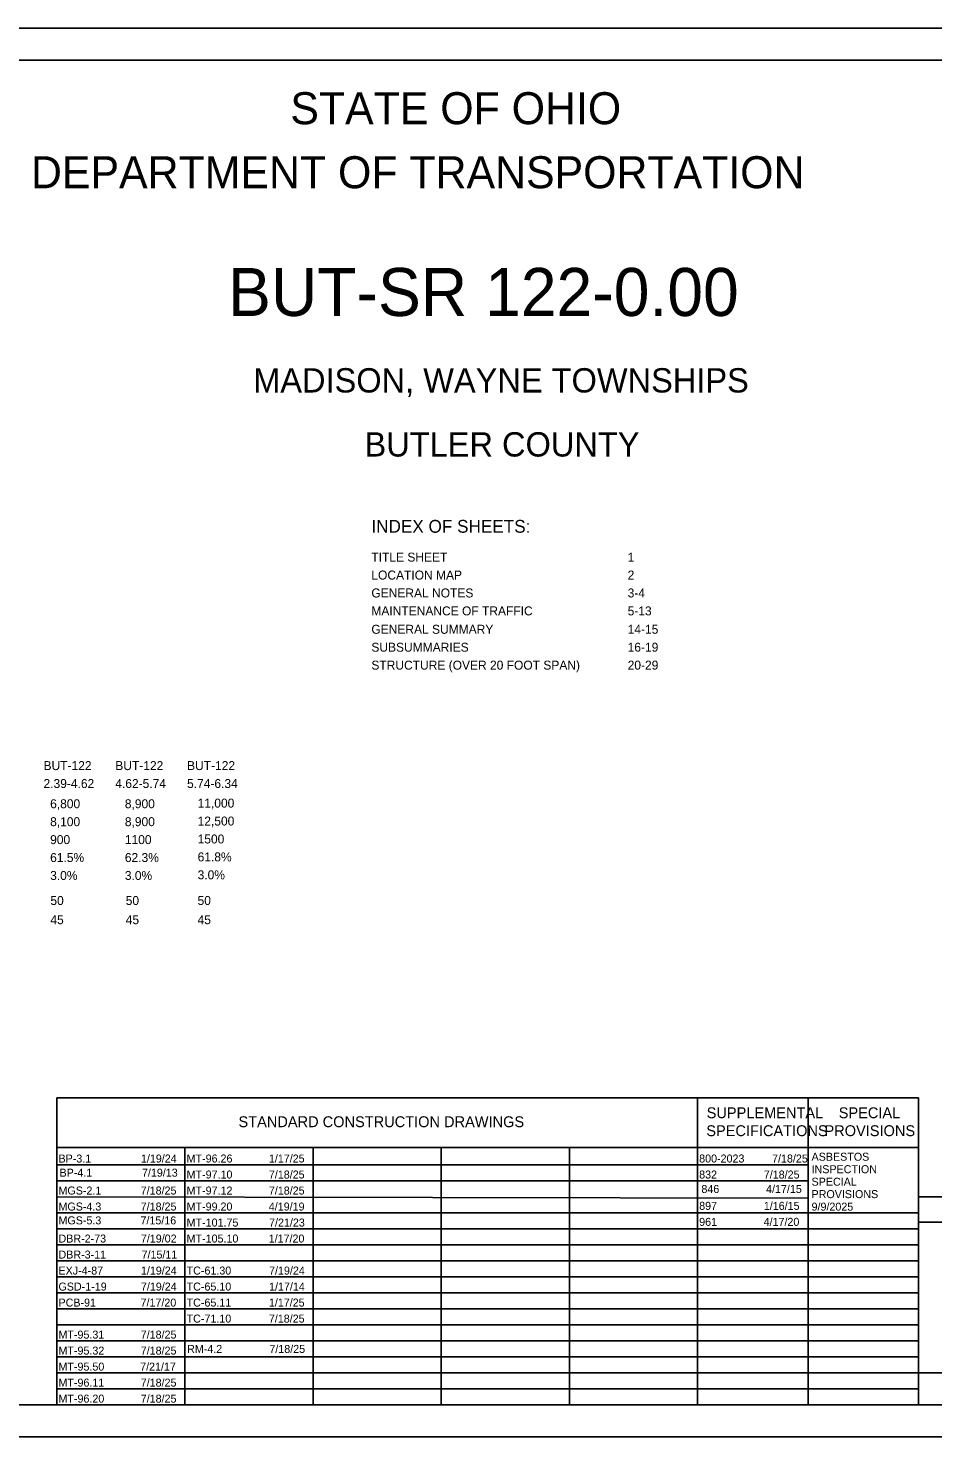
# Model space of a CAD drawing. Extents: x -11.1 to 43.5, y 0 to 22.
# Drawn here: x 9.7 to 23.82, y 0 to 22 of the extents above; entities that cross this region are included whole.
import ezdxf

# ---------------------------------------------------------------- set-up
doc = ezdxf.new("R2010")
doc.units = 0
for name, color, linetype in [('Default', 7, 'Continuous'), ('SH_Border', 7, 'Continuous'), ('SH_Cut_Line', 7, 'Continuous'), ('SH_Data', 7, 'Continuous'), ('SH_Text', 7, 'Continuous')]:
    doc.layers.add(name, color=color, linetype=linetype)

msp = doc.modelspace()

# ---------------------------------------------------------------- linework, layer by layer
at = {"layer": 'SH_Border'}
msp.add_lwpolyline([(1.5, 21.5), (33.5, 21.5), (33.5, 0.5), (1.5, 0.5)], close=True, dxfattribs=at)
at = {"layer": 'SH_Cut_Line'}
msp.add_lwpolyline([(0, 0), (34, 0), (34, 22), (0, 22)], close=True, dxfattribs=at)
at = {"layer": 'SH_Data'}
for p, q in [((10.15, 5.292), (23.6, 5.292)), ((10.15, 0.5), (10.15, 5.292)), ((20.15, 0.5), (20.15, 5.292)), ((21.875, 0.5), (21.875, 5.292)), ((23.6, 0.5), (23.6, 5.292)), ((10.15, 4.521), (23.6, 4.521)), ((12.15, 0.5), (12.15, 4.521)), ((14.15, 0.5), (14.15, 4.521)), ((16.15, 0.5), (16.15, 4.521)), ((18.15, 0.5), (18.15, 4.521)), ((10.15, 4.25), (21.875, 4.25)), ((10.15, 4), (21.875, 4)), ((10.15, 3.75), (21.875, 3.728)), ((23.6, 0.5), (23.6, 3.75)), ((23.6, 3.75), (26.4, 3.75)), ((10.15, 3.5), (23.6, 3.5)), ((23.6, 3.35), (26.4, 3.35)), ((10.15, 3.25), (23.6, 3.25)), ((10.15, 3), (23.6, 3)), ((10.15, 2.75), (23.6, 2.75)), ((10.15, 2.5), (23.6, 2.5)), ((10.15, 2.25), (23.6, 2.25)), ((10.15, 2), (23.6, 2)), ((10.15, 1.75), (23.6, 1.75)), ((10.15, 1.5), (23.6, 1.5)), ((10.15, 1.25), (23.6, 1.25)), ((10.15, 1), (23.6, 1)), ((10.15, 0.75), (23.6, 0.75)), ((23.6, 0.5), (26.4, 0.5))]:
    msp.add_line(p, q, dxfattribs=at)
msp.add_lwpolyline([(23.6, 0.5), (23.6, 1), (26.4, 1), (26.4, 0.5)], close=True, dxfattribs=at)

# ---------------------------------------------------------------- texts
at = {"layer": 'Default'}
for s, p in [('BP-3.1', (10.176, 4.284)), ('1/19/24', (11.463, 4.284)), ('MT-96.26', (12.176, 4.284)), ('1/17/25', (13.46, 4.284)), ('800-2023', (20.176, 4.284)), ('7/18/25', (21.314, 4.284)), ('BP-4.1', (10.192, 4.063)), ('7/19/13', (11.479, 4.063)), ('MT-97.10', (12.176, 4.034)), ('7/18/25', (13.46, 4.034)), ('832', (20.176, 4.034)), ('7/18/25', (21.185, 4.034)), ('MGS-2.1', (10.176, 3.784)), ('7/18/25', (11.46, 3.784)), ('MT-97.12', (12.176, 3.784)), ('7/18/25', (13.46, 3.784)), ('846', (20.211, 3.808)), ('4/17/15', (21.22, 3.808)), ('MGS-4.3', (10.176, 3.534)), ('7/18/25', (11.46, 3.534)), ('MT-99.20', (12.176, 3.534)), ('4/19/19', (13.459, 3.534)), ('897', (20.176, 3.545)), ('1/16/15', (21.185, 3.545)), ('MGS-5.3', (10.176, 3.318)), ('7/15/16', (11.456, 3.318)), ('MT-101.75', (12.176, 3.284)), ('7/21/23', (13.463, 3.284)), ('961', (20.176, 3.295)), ('4/17/20', (21.182, 3.295)), ('DBR-2-73', (10.176, 3.034)), ('7/19/02', (11.462, 3.034)), ('MT-105.10', (12.176, 3.034)), ('1/17/20', (13.457, 3.034)), ('DBR-3-11', (10.176, 2.784)), ('7/15/11', (11.473, 2.784)), ('EXJ-4-87', (10.176, 2.534)), ('1/19/24', (11.463, 2.534)), ('TC-61.30', (12.176, 2.534)), ('7/19/24', (13.463, 2.534)), ('GSD-1-19', (10.176, 2.284)), ('7/19/24', (11.463, 2.284)), ('TC-65.10', (12.176, 2.284)), ('1/17/14', (13.463, 2.284)), ('PCB-91', (10.176, 2.034)), ('7/17/20', (11.457, 2.034)), ('TC-65.11', (12.176, 2.034)), ('1/17/25', (13.46, 2.034)), ('TC-71.10', (12.176, 1.784)), ('7/18/25', (13.46, 1.784)), ('MT-95.31', (10.176, 1.534)), ('7/18/25', (11.46, 1.534)), ('MT-95.32', (10.176, 1.284)), ('7/18/25', (11.46, 1.284)), ('RM-4.2', (12.183, 1.31)), ('7/18/25', (13.468, 1.31)), ('MT-95.50', (10.176, 1.034)), ('7/21/17', (11.451, 1.034)), ('MT-96.11', (10.176, 0.784)), ('7/18/25', (11.46, 0.784)), ('MT-96.20', (10.176, 0.534)), ('7/18/25', (11.46, 0.534))]:
    msp.add_text(s, height=0.125, dxfattribs=at).set_placement(p)
at = {"layer": 'SH_Text'}
for s, height, p in [('STATE OF OHIO', 0.5, (13.795, 20.5)), ('DEPARTMENT OF TRANSPORTATION', 0.5, (9.747, 19.5)), ('BUT-SR 122-0.00', 0.75, (12.823, 17.505)), ('MADISON, WAYNE TOWNSHIPS', 0.38, (13.215, 16.31)), ('BUTLER COUNTY', 0.38, (14.953, 15.31)), ('INDEX OF SHEETS:', 0.2, (15.06, 14.12)), ('TITLE SHEET', 0.14, (15.06, 13.669)), ('1', 0.14, (19.06, 13.669)), ('LOCATION MAP', 0.14, (15.06, 13.389)), ('2', 0.14, (19.06, 13.389)), ('GENERAL NOTES', 0.14, (15.06, 13.109)), ('3-4', 0.14, (19.06, 13.109)), ('MAINTENANCE OF TRAFFIC', 0.14, (15.06, 12.829)), ('5-13', 0.14, (19.06, 12.829)), ('GENERAL SUMMARY', 0.14, (15.06, 12.542)), ('14-15', 0.14, (19.06, 12.542)), ('SUBSUMMARIES', 0.14, (15.06, 12.262)), ('16-19', 0.14, (19.06, 12.262)), ('STRUCTURE (OVER 20 FOOT SPAN)', 0.14, (15.06, 11.982)), ('20-29', 0.14, (19.06, 11.982)), ('BUT-122', 0.14, (9.943, 10.413)), ('BUT-122', 0.14, (11.063, 10.413)), ('BUT-122', 0.14, (12.183, 10.413)), ('2.39-4.62', 0.14, (9.943, 10.133)), ('4.62-5.74', 0.14, (11.063, 10.133)), ('5.74-6.34', 0.14, (12.183, 10.133)), ('6,800', 0.14, (10.046, 9.817)), ('8,900', 0.14, (11.212, 9.817)), ('11,000', 0.14, (12.348, 9.827)), ('12,500', 0.14, (12.348, 9.547)), ('8,100', 0.14, (10.046, 9.537)), ('8,900', 0.14, (11.212, 9.537)), ('900', 0.14, (10.046, 9.257)), ('1100', 0.14, (11.212, 9.257)), ('1500', 0.14, (12.348, 9.267)), ('61.5%', 0.14, (10.046, 8.977)), ('62.3%', 0.14, (11.212, 8.977)), ('61.8%', 0.14, (12.348, 8.987)), ('3.0%', 0.14, (10.046, 8.697)), ('3.0%', 0.14, (11.212, 8.697)), ('3.0%', 0.14, (12.348, 8.707)), ('50', 0.14, (10.05, 8.306)), ('50', 0.14, (11.226, 8.306)), ('50', 0.14, (12.347, 8.306)), ('45', 0.14, (10.05, 8.006)), ('45', 0.14, (11.226, 8.006)), ('45', 0.14, (12.347, 8.006)), ('SUPPLEMENTAL', 0.17, (20.293, 4.976)), ('SPECIAL', 0.17, (22.354, 4.976)), ('STANDARD CONSTRUCTION DRAWINGS', 0.17, (12.986, 4.836)), ('SPECIFICATIONS', 0.17, (20.287, 4.696)), ('PROVISIONS', 0.17, (22.132, 4.696)), ('ASBESTOS ', 0.125, (21.93, 4.312)), ('INSPECTION', 0.125, (21.93, 4.117)), ('SPECIAL ', 0.125, (21.93, 3.922)), ('PROVISIONS', 0.125, (21.93, 3.728)), ('9/9/2025', 0.125, (21.93, 3.532))]:
    msp.add_text(s, height=height, dxfattribs=at).set_placement(p)

doc.saveas('drawing.dxf')
